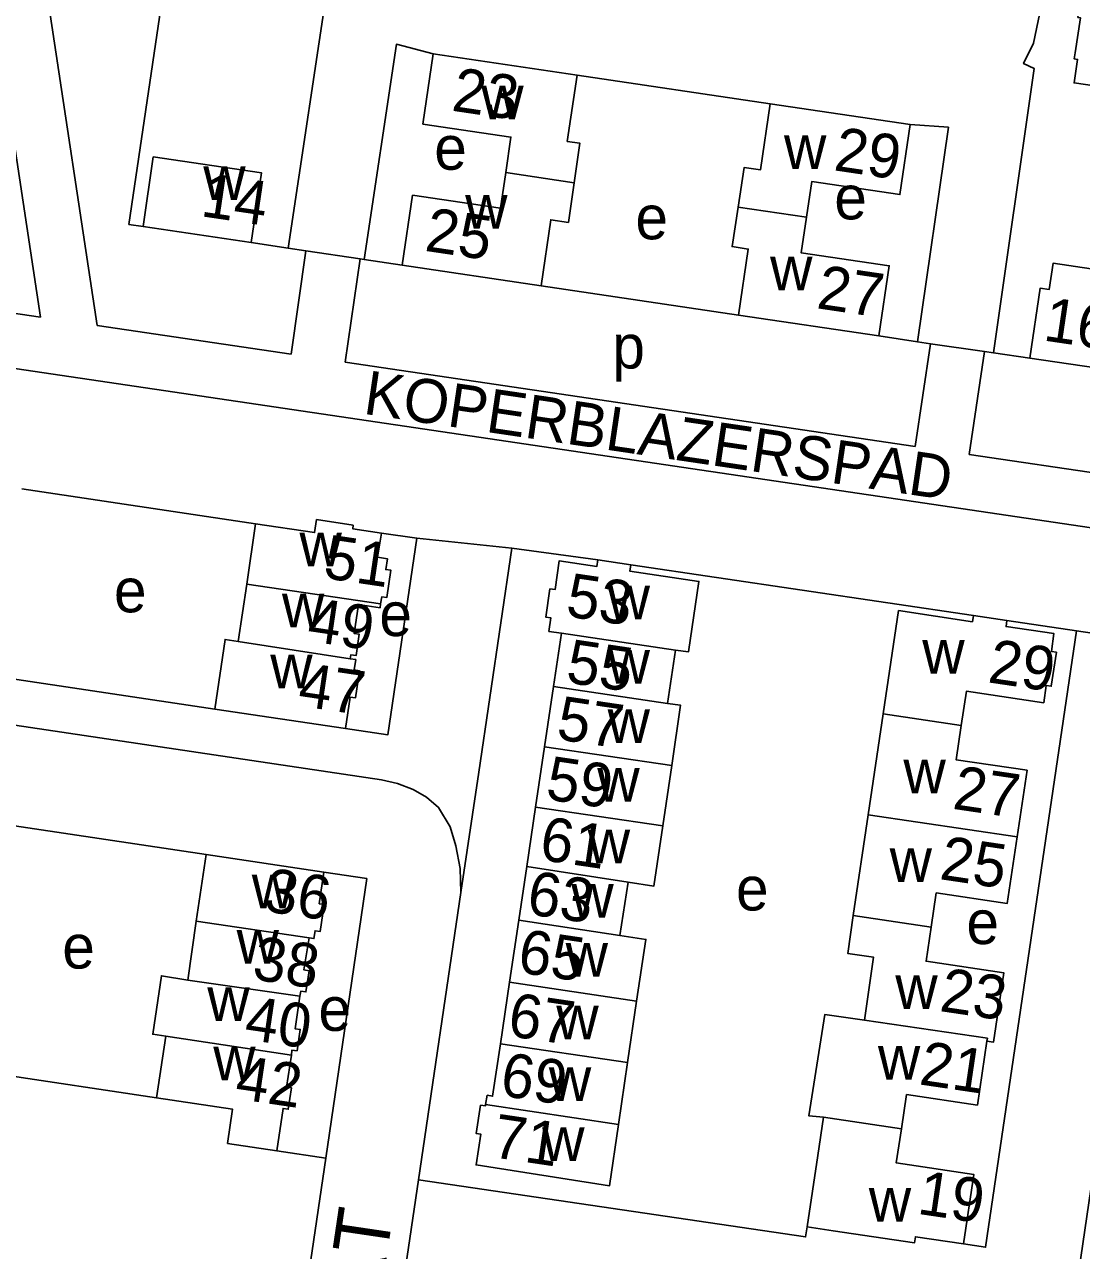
# Model space of a CAD drawing. Extents: x 163012 to 165277, y 382513 to 383987.
# Drawn here: x 164368.9 to 164465.3, y 382967.6 to 383079.5 of the extents above; entities that cross this region are included whole.
import ezdxf

# ---------------------------------------------------------------- set-up
doc = ezdxf.new("R2010")
doc.units = 0
for name, color, linetype in [('BLT_Basislijn', 7, 'Continuous'), ('BLT_Bebouwing', 7, 'Continuous'), ('BLT_Centroide', 7, 'Continuous'), ('BLT_Huisnummer', 7, 'Continuous'), ('BLT_Huisnummer_ tussenligend', 7, 'Continuous'), ('BLT_Onderdoorgang_en_onderverdeling', 7, 'Continuous'), ('BLT_Onderverdeling_panden', 7, 'Continuous'), ('BLT_Straatnaam', 7, 'Continuous'), ('BLT_Straatnaam_verkleind', 7, 'Continuous'), ('BLT_Vlakafsluiter', 7, 'Continuous')]:
    doc.layers.add(name, color=color, linetype=linetype)

msp = doc.modelspace()

# ---------------------------------------------------------------- linework, layer by layer
at = {"layer": 'BLT_Basislijn'}
for p, q in [((164399.04, 383200.86), (164378.38, 383061.27)), ((164365.6, 383117.39), (164375.5, 383052.06)), ((164419.3, 383074.9), (164436.92, 383072.29)), ((164603.19, 383013.36), (164235.92, 383067.64)), ((164379.68, 383061.09), (164378.38, 383061.27)), ((164392.94, 383059.13), (164389.56, 383059.63)), ((164394.54, 383058.89), (164392.94, 383059.13)), ((164394.54, 383058.89), (164393.19, 383049.45)), ((164394.54, 383058.89), (164399.49, 383058.15)), ((164399.49, 383058.15), (164398.14, 383048.71)), ((164399.86, 383058.09), (164399.49, 383058.15)), ((164403.33, 383057.57), (164399.86, 383058.09)), ((164434.02, 383053.02), (164416.02, 383055.69)), ((164393.19, 383049.45), (164375.5, 383052.06)), ((164450.37, 383050.56), (164446.84, 383051.13)), ((164451.54, 383050.4), (164450.37, 383050.56)), ((164451.54, 383050.4), (164450.14, 383041.03)), ((164451.54, 383050.4), (164456.49, 383049.69)), ((164456.49, 383049.69), (164455.09, 383040.3)), ((164457.3, 383049.57), (164456.49, 383049.69)), ((164460.63, 383049.07), (164457.3, 383049.57)), ((164450.14, 383041.03), (164398.14, 383048.71)), ((164486.79, 383035.61), (164455.09, 383040.3)), ((164368.63, 383037.16), (164389.96, 383033.96)), ((164401.43, 383033.12), (164404.66, 383032.65)), ((164404.66, 383032.65), (164413.35, 383031.73)), ((164413.35, 383031.73), (164421.2, 383030.67)), ((164424.19, 383030.22), (164455.47, 383025.59)), ((164458.52, 383025.13), (164464.88, 383024.19)), ((164386.22, 383017.06), (164366.08, 383020.07)), ((164366.5, 383006.6), (164385.44, 383003.79)), ((164404.81, 382974.11), (164408.7, 383000.32)), ((164363.16, 382984.25), (164380.91, 382981.59)), ((164391.89, 382976.74), (164396.35, 382976.08)), ((164396.35, 382976.08), (164394.84, 382965.76))]:
    msp.add_line(p, q, dxfattribs=at)
for points in [[(164411.69, 383198.98), (164412.05, 383198.86), (164412.43, 383198.68), (164412.81, 383198.36), (164413.09, 383197.98), (164413.26, 383197.52), (164413.39, 383196.9), (164413.43, 383196.13), (164413.32, 383194.98), (164397.86, 383091), (164398.09, 383085.94), (164398.23, 383084.84), (164396.72, 383084.46), (164392.94, 383059.13)], [(164480.56, 383188.75), (164479.75, 383188.76), (164479.26, 383188.66), (164478.69, 383188.34), (164478.17, 383187.84), (164477.65, 383186.95), (164477.28, 383185.55), (164476, 383178.07), (164461.8, 383081.93), (164460.94, 383077.84), (164460.05, 383075.97), (164461.02, 383075.51), (164457.3, 383049.57)], [(164359.03, 383106.48), (164362.13, 383106.93), (164370.33, 383052.83)], [(164370.33, 383052.83), (164251.23, 383070.43), (164259.63, 383102.63), (164263.34, 383101.65)], [(164406.17, 383076.85), (164402.8, 383077.73), (164399.86, 383058.09)], [(164449.7, 383070.4), (164453.18, 383070.16), (164450.37, 383050.56)], [(164404.66, 383032.65), (164402.03, 383014.71), (164398.15, 383015.28)], [(164408.7, 383000.32), (164410.33, 383011.31), (164413.35, 383031.73)], [(164464.88, 383024.19), (164456.57, 382967.95), (164454.57, 382968.25)], [(164455.28, 382898.84), (164473.44, 383022.93), (164464.88, 383024.19)], [(164340.51, 383010.46), (164341.09, 383012.72), (164341.82, 383014.3), (164342.85, 383015.75), (164344.2, 383016.75), (164345.53, 383017.52), (164347.39, 383018.09), (164348.84, 383018.34), (164350.62, 383018.17), (164401.43, 383010.61), (164402.91, 383010.27), (164404.33, 383009.72), (164405.54, 383009.03), (164406.65, 383008.08), (164407.71, 383006.32), (164408.24, 383004.59), (164408.61, 383002.5), (164408.7, 383000.32)], [(164396.19, 383002.18), (164400.1, 383001.59), (164396.35, 382976.08)], [(164440.29, 382969.81), (164440.15, 382968.89), (164404.81, 382974.11)]]:
    msp.add_lwpolyline(points, dxfattribs=at)
at = {"layer": 'BLT_Bebouwing'}
for p, q in [((164406.17, 383076.85), (164419.3, 383074.9)), ((164436.92, 383072.29), (164449.7, 383070.4)), ((164389.56, 383059.63), (164379.68, 383061.09)), ((164403.33, 383057.57), (164416.02, 383055.69)), ((164446.84, 383051.13), (164434.02, 383053.02)), ((164470.52, 383047.62), (164460.63, 383049.07)), ((164398.87, 383033.85), (164395.51, 383034.35)), ((164421.2, 383030.67), (164424.19, 383030.22)), ((164389.14, 383028.46), (164388.36, 383023.23)), ((164455.47, 383025.59), (164458.52, 383025.13)), ((164417.86, 383023.97), (164417.14, 383019.12)), ((164428.28, 383022.44), (164427.55, 383017.58)), ((164417.14, 383019.12), (164416.32, 383013.62)), ((164447.24, 383016.62), (164445.87, 383007.41)), ((164416.32, 383013.62), (164415.51, 383008.12)), ((164427.93, 383011.9), (164427.11, 383006.41)), ((164414.7, 383002.68), (164415.51, 383008.12)), ((164444.5, 382998.21), (164445.87, 383007.41)), ((164413.98, 382997.8), (164414.7, 383002.68)), ((164423.95, 383001.27), (164423.2, 382996.4)), ((164384.54, 382997.7), (164383.77, 382992.32)), ((164413.98, 382997.8), (164413.13, 382992.13)), ((164413.13, 382992.13), (164412.3, 382986.5)), ((164424.73, 382990.41), (164423.9, 382984.79)), ((164423.07, 382979.16), (164423.9, 382984.79))]:
    msp.add_line(p, q, dxfattribs=at)
for points in [[(164465.48, 383083.36), (164465.01, 383080.18), (164465.23, 383080.14), (164464.75, 383076.94), (164464.67, 383076.39), (164464.97, 383076.35), (164464.65, 383074.2), (164469.18, 383073.53), (164469.49, 383075.68), (164474.55, 383074.93), (164474.63, 383075.48), (164475.57, 383081.87)], [(164412.78, 383066.02), (164413.26, 383069.26), (164405.23, 383070.45), (164406.17, 383076.85)], [(164419.3, 383074.9), (164418.4, 383068.86), (164419.55, 383068.69), (164419.03, 383065.09)], [(164433.99, 383062.86), (164434.53, 383066.47), (164436.02, 383066.26), (164436.92, 383072.29)], [(164449.7, 383070.4), (164448.76, 383064.01), (164440.71, 383065.19), (164440.23, 383061.94)], [(164379.68, 383061.09), (164380.61, 383067.45), (164390.5, 383065.99), (164389.56, 383059.63)], [(164403.33, 383057.57), (164404.28, 383063.95), (164412.3, 383062.78), (164412.78, 383066.02)], [(164419.03, 383065.09), (164418.5, 383061.47), (164416.89, 383061.71), (164416.02, 383055.69)], [(164434.02, 383053.02), (164434.92, 383059.04), (164433.44, 383059.26), (164433.99, 383062.86)], [(164440.23, 383061.94), (164439.75, 383058.69), (164447.79, 383057.51), (164446.84, 383051.13)], [(164460.63, 383049.07), (164461.57, 383055.47), (164462.38, 383055.36), (164462.73, 383057.74), (164471.12, 383056.51), (164470.78, 383054.12), (164471.46, 383054.02), (164470.52, 383047.62)], [(164389.96, 383033.96), (164389.14, 383028.46)], [(164395.51, 383034.35), (164395.33, 383033.16), (164389.96, 383033.96)], [(164401.43, 383033.12), (164398.82, 383033.51), (164398.87, 383033.85)], [(164401.36, 383026.65), (164401.46, 383027.3), (164401.93, 383027.23), (164402.31, 383029.72), (164401.84, 383029.79), (164401.98, 383030.77), (164401.08, 383030.92), (164401.43, 383033.12)], [(164417.86, 383023.97), (164416.72, 383024.14), (164416.9, 383025.38), (164416.45, 383025.44), (164416.82, 383028.03), (164417.28, 383027.96), (164417.67, 383030.59), (164421.11, 383030.08), (164421.2, 383030.67)], [(164424.19, 383030.22), (164424.11, 383029.64), (164430.41, 383028.7), (164429.46, 383022.27), (164428.28, 383022.44)], [(164401.36, 383026.65), (164401.31, 383026.3), (164399.34, 383026.6), (164398.94, 383023.96), (164399.42, 383023.89), (164399.12, 383021.94), (164398.65, 383022.01), (164398.6, 383021.64)], [(164455.47, 383025.59), (164455.38, 383025.03), (164448.64, 383026.04), (164447.24, 383016.62)], [(164458.52, 383025.13), (164458.44, 383024.58), (164462.82, 383023.94), (164462.58, 383022.32), (164463.04, 383022.25), (164462.57, 383019.14), (164462.12, 383019.21), (164461.88, 383017.63), (164454.82, 383018.68), (164454.35, 383015.56)], [(164388.36, 383023.23), (164387.17, 383023.41), (164386.22, 383017.06)], [(164398.15, 383015.28), (164398.58, 383018.14), (164399.06, 383018.07), (164399.43, 383020.56), (164398.96, 383020.63), (164399.1, 383021.57), (164398.6, 383021.64)], [(164386.22, 383017.06), (164398.15, 383015.28)], [(164427.55, 383017.58), (164428.74, 383017.4), (164427.93, 383011.9)], [(164454.35, 383015.56), (164453.88, 383012.44), (164460.36, 383011.47), (164459.46, 383005.39)], [(164427.11, 383006.41), (164426.3, 383000.91), (164423.95, 383001.27)], [(164459.46, 383005.39), (164458.56, 382999.32), (164452.07, 383000.28), (164451.61, 382997.16)], [(164385.44, 383003.79), (164384.54, 382997.7)], [(164396.19, 383002.18), (164385.44, 383003.79)], [(164394.84, 382996.17), (164395.28, 382996.11), (164395.39, 382996.82), (164395.84, 382996.75), (164396.21, 382999.23), (164395.76, 382999.29), (164396.19, 383002.18)], [(164444.5, 382998.21), (164443.99, 382994.76), (164446.36, 382994.41), (164445.52, 382988.67)], [(164456.7, 382986.75), (164457.31, 382986.66), (164458.23, 382992.99), (164451.15, 382994.04), (164451.61, 382997.16)], [(164394, 382990.85), (164394.07, 382991.31), (164394.54, 382991.24), (164394.84, 382993.18), (164394.36, 382993.25), (164394.84, 382996.17)], [(164423.2, 382996.4), (164425.57, 382996.03), (164424.73, 382990.41)], [(164383.77, 382992.32), (164381.36, 382992.72), (164380.57, 382987.38), (164381.75, 382987.22)], [(164393.24, 382985.47), (164393.27, 382985.94), (164393.74, 382985.87), (164394.03, 382987.82), (164393.56, 382987.89), (164394, 382990.85)], [(164445.52, 382988.67), (164441.92, 382989.19), (164440.45, 382979.93), (164441.78, 382979.82)], [(164381.75, 382987.22), (164380.91, 382981.59)], [(164412.3, 382986.5), (164411.59, 382981.73), (164411.09, 382981.81), (164410.95, 382980.96)], [(164448.9, 382978.76), (164449.37, 382981.88), (164455.83, 382980.92), (164456.7, 382986.75)], [(164391.89, 382976.74), (164392.47, 382980.62), (164392.94, 382980.54), (164393.24, 382982.49), (164392.76, 382982.56), (164393.24, 382985.47)], [(164380.91, 382981.59), (164387.86, 382980.54), (164387.39, 382977.42), (164391.89, 382976.74)], [(164410.95, 382980.96), (164410.93, 382980.84), (164410.48, 382980.91), (164410.07, 382978.33), (164410.52, 382978.26), (164410.08, 382975.46), (164422.24, 382973.54), (164423.07, 382979.16)], [(164441.78, 382979.82), (164441.26, 382976.32), (164440.29, 382969.81)], [(164454.57, 382968.25), (164455.51, 382974.58), (164448.43, 382975.64), (164448.9, 382978.76)], [(164440.29, 382969.81), (164442.67, 382969.45), (164450.09, 382968.35), (164450.18, 382968.9), (164454.57, 382968.25)]]:
    msp.add_lwpolyline(points, dxfattribs=at)
at = {"layer": 'BLT_Onderdoorgang_en_onderverdeling'}
for p, q in [((164417.86, 383023.97), (164428.28, 383022.44)), ((164417.14, 383019.12), (164427.55, 383017.58)), ((164454.35, 383015.56), (164447.24, 383016.62)), ((164416.32, 383013.62), (164427.93, 383011.9)), ((164415.51, 383008.12), (164427.11, 383006.41)), ((164445.87, 383007.41), (164459.46, 383005.39)), ((164423.95, 383001.27), (164414.7, 383002.68)), ((164451.61, 382997.16), (164444.5, 382998.21)), ((164413.98, 382997.8), (164423.2, 382996.4)), ((164413.13, 382992.13), (164424.73, 382990.41)), ((164412.3, 382986.5), (164423.9, 382984.79)), ((164410.95, 382980.96), (164423.07, 382979.16)), ((164448.9, 382978.76), (164441.78, 382979.82))]:
    msp.add_line(p, q, dxfattribs=at)
msp.add_lwpolyline([(164445.52, 382988.67), (164456.74, 382987.02), (164456.7, 382986.75)], dxfattribs=at)
at = {"layer": 'BLT_Onderverdeling_panden'}
for p, q in [((164412.78, 383066.02), (164419.03, 383065.09)), ((164433.99, 383062.86), (164440.23, 383061.94)), ((164389.14, 383028.46), (164401.36, 383026.65)), ((164388.36, 383023.23), (164398.6, 383021.64)), ((164384.54, 382997.7), (164394.84, 382996.17)), ((164383.77, 382992.32), (164394, 382990.85)), ((164381.75, 382987.22), (164393.24, 382985.47))]:
    msp.add_line(p, q, dxfattribs=at)
at = {"layer": 'BLT_Vlakafsluiter'}
msp.add_line((164403.5, 382965.24), (164404.81, 382974.11), dxfattribs=at)

# ---------------------------------------------------------------- texts
at = {"layer": 'BLT_Centroide'}
for s, p in [('w', (164410.55, 383070.88)), ('e', (164406.26, 383066.28)), ('w', (164438.18, 383066.33)), ('w', (164385.18, 383063.53)), ('w', (164409.08, 383060.91)), ('e', (164442.77, 383061.75)), ('e', (164424.62, 383059.93)), ('w', (164436.91, 383055.27)), ('p', (164422.51, 383048.14)), ('w', (164393.96, 383030.08)), ('e', (164377.03, 383025.89)), ('w', (164422.08, 383025.24)), ('w', (164392.36, 383024.52)), ('e', (164401.25, 383023.72)), ('w', (164450.8, 383020.28)), ('w', (164391.29, 383018.96)), ('w', (164422.08, 383019.38)), ('w', (164422.08, 383013.97)), ('w', (164421.14, 383008.6)), ('w', (164449.08, 383009.36)), ('w', (164420.27, 383002.98)), ('w', (164447.82, 383001.29)), ('w', (164389.61, 382998.86)), ('e', (164433.8, 382998.68)), ('w', (164418.77, 382998.02)), ('e', (164454.83, 382995.61)), ('w', (164388.22, 382993.83)), ('e', (164372.31, 382993.38)), ('w', (164418.25, 382992.64)), ('w', (164448.34, 382989.68)), ('w', (164385.55, 382988.59)), ('e', (164395.69, 382987.69)), ('w', (164417.4, 382986.91)), ('w', (164386.09, 382983.19)), ('w', (164446.75, 382983.25)), ('w', (164416.72, 382981.29)), ('w', (164416.11, 382975.81)), ('w', (164445.92, 382970.28))]:
    msp.add_text(s, height=4, dxfattribs=at).set_placement(p)
at = {"layer": 'BLT_Huisnummer'}
for s, rotation, p in [('23', 351.5824, (164407.75, 383071.68)), ('29', 351.5824, (164442.63, 383066.24)), ('14', 351.5826, (164384.85, 383062.05)), ('25', 351.5824, (164405.3, 383058.89)), ('27', 351.5824, (164441.06, 383053.65)), ('16', 351.5826, (164461.75, 383050.71)), ('51', 351.583, (164396.03, 383029.04)), ('53', 351.581, (164418.16, 383025.54)), ('55', 351.581, (164418.18, 383019.5)), ('29', 351.581, (164456.69, 383019.51)), ('47', 351.583, (164393.72, 383017.37)), ('57', 351.583, (164417.31, 383014.32)), ('59', 351.583, (164416.33, 383008.84)), ('27', 351.581, (164453.47, 383007.97)), ('61', 351.583, (164415.75, 383003.33)), ('25', 351.581, (164452.28, 383001.55)), ('36', 351.581, (164390.6, 382998.63)), ('63', 351.583, (164414.59, 382998.37)), ('65', 351.583, (164413.76, 382993.05)), ('38', 351.581, (164389.55, 382992.41)), ('23', 351.581, (164452.28, 382989.51)), ('67', 351.583, (164412.85, 382987.25)), ('69', 351.583, (164412.16, 382981.8)), ('21', 351.581, (164450.42, 382982.82)), ('42', 351.581, (164387.98, 382981.52)), ('71', 351.583, (164411.44, 382976.18)), ('19', 351.581, (164450.25, 382971.01))]:
    msp.add_text(s, height=4, rotation=rotation, dxfattribs=at).set_placement(p)
at = {"layer": 'BLT_Huisnummer_ tussenligend'}
for s, rotation, p in [('49', 351.583, (164394.55, 383023.29)), ('40', 351.581, (164388.83, 382986.94))]:
    msp.add_text(s, height=4, rotation=rotation, dxfattribs=at).set_placement(p)
at = {"layer": 'BLT_Straatnaam'}
for s, rotation, p in [('CONTRABASSTRAAT', 81.5825, (164467.27, 382909.28)), ('CELLOSTRAAT', 81.5824, (164395.45, 382923.28))]:
    msp.add_text(s, height=5, rotation=rotation, dxfattribs=at).set_placement(p)
at = {"layer": 'BLT_Straatnaam_verkleind'}
msp.add_text('KOPERBLAZERSPAD', height=4, rotation=351.5928, dxfattribs=at).set_placement((164399.69, 383044.02))

doc.saveas('drawing.dxf')
